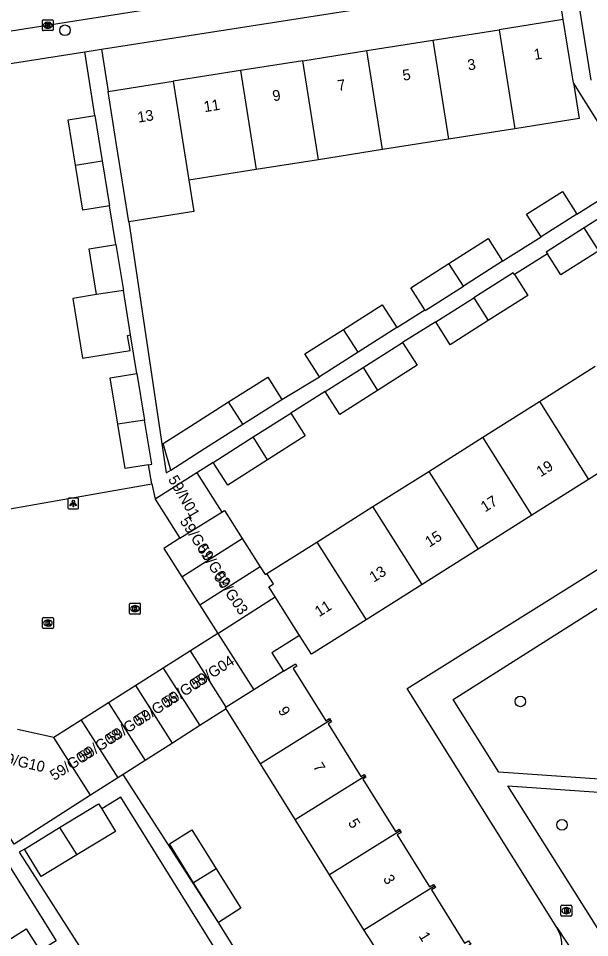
# Model space of a CAD drawing. Extents: x 160077 to 160945, y 386481 to 387498.
# Drawn here: x 160315.7 to 160368.6, y 387143.3 to 387228.4 of the extents above; entities that cross this region are included whole.
import ezdxf

# ---------------------------------------------------------------- set-up
doc = ezdxf.new("R2010")
doc.units = 0
for name, color, linetype in [('IMGEO_Boom', 7, 'Continuous'), ('IMGEO_Brandkraan', 7, 'Continuous'), ('IMGEO_Kolk', 7, 'Continuous'), ('IMGEO_Lichtpunt', 7, 'Continuous'), ('IMGEO_Pand', 7, 'Continuous'), ('IMGEO_Pand_nummerreeks', 7, 'Continuous'), ('IMGEO_Rijbaan_lokaal_open', 7, 'Continuous'), ('IMGEO_Voetpad_open', 7, 'Continuous')]:
    doc.layers.add(name, color=color, linetype=linetype)

msp = doc.modelspace()

# ---------------------------------------------------------------- linework, layer by layer
at = {"layer": 'IMGEO_Boom'}
for centre in [(160320.047, 387227.258), (160362.151, 387165.177), (160365.998, 387153.759)]:
    msp.add_circle(centre, 0.489, dxfattribs=at)
at = {"layer": 'IMGEO_Brandkraan'}
for p, q in [((160365.9, 387145.394), (160365.9, 387146.246)), ((160365.975, 387146.32), (160366.827, 387146.32)), ((160366.388, 387146.1), (160366.413, 387146.1)), ((160366.901, 387146.246), (160366.901, 387145.394)), ((160366.827, 387145.32), (160365.975, 387145.32)), ((160366.411, 387145.54), (160366.386, 387145.54))]:
    msp.add_line(p, q, dxfattribs=at)
for points in [[(160365.9, 387145.394), (160365.9, 387146.246)], [(160365.975, 387146.32), (160366.827, 387146.32)], [(160366.248, 387146.02), (160366.248, 387145.62), (160366.461, 387145.62)], [(160366.479, 387146.02), (160366.248, 387146.02)], [(160366.427, 387145.939), (160366.373, 387145.939), (160366.373, 387145.863)], [(160366.373, 387145.863), (160366.426, 387145.863)], [(160366.435, 387145.787), (160366.373, 387145.787), (160366.373, 387145.706)], [(160366.901, 387146.246), (160366.901, 387145.394)], [(160366.827, 387145.32), (160365.975, 387145.32)], [(160366.373, 387145.706), (160366.435, 387145.706)]]:
    msp.add_lwpolyline(points, dxfattribs=at)
for centre, radius, start, end in [((160365.977, 387146.244), 0.0765, 91.55205, 178.44795), ((160365.977, 387146.244), 0.0765, 91.55205, 178.44795), ((160366.428, 387145.901), 0.0379, 267.82845, 90.93552), ((160366.436, 387145.746), 0.0404, 269.87594, 90.50774), ((160366.483, 387145.875), 0.145, 59.4692, 91.53667), ((160366.508, 387145.922), 0.0922, 285.51372, 58.15012), ((160366.513, 387145.73), 0.105, 301.31148, 78.98903), ((160366.825, 387146.244), 0.0765, 1.55205, 88.44795), ((160366.825, 387146.244), 0.0765, 1.55205, 88.44795), ((160365.977, 387145.396), 0.0765, 181.55205, 268.44795), ((160365.977, 387145.396), 0.0765, 181.55205, 268.44795), ((160366.467, 387145.871), 0.251, 268.66757, 293.53466), ((160366.825, 387145.396), 0.0765, 271.55205, 358.44795), ((160366.825, 387145.396), 0.0765, 271.55205, 358.44795)]:
    msp.add_arc(centre, radius, start, end, dxfattribs=at)
for centre, major_axis, ratio, start_param, end_param in [((160366.387, 387145.82), (-0.387, 0.002), 0.722429, 4.712389, 7.853982), ((160366.412, 387145.82), (-0.39, 0.002), 0.717154, 1.570796, 4.712389)]:
    msp.add_ellipse(centre, major_axis=major_axis, ratio=ratio, start_param=start_param, end_param=end_param, dxfattribs=at)
at = {"layer": 'IMGEO_Kolk'}
for p, q in [((160318.032, 387228.223), (160318.884, 387228.223)), ((160317.957, 387227.297), (160317.957, 387228.149)), ((160318.468, 387227.443), (160318.443, 387227.443)), ((160318.445, 387228.003), (160318.47, 387228.003)), ((160318.958, 387228.149), (160318.958, 387227.297)), ((160318.884, 387227.223), (160318.032, 387227.223)), ((160326.012, 387173.333), (160326.012, 387174.185)), ((160326.087, 387174.259), (160326.939, 387174.259)), ((160326.5, 387174.039), (160326.525, 387174.039)), ((160327.013, 387174.185), (160327.013, 387173.333)), ((160326.939, 387173.259), (160326.087, 387173.259)), ((160326.523, 387173.479), (160326.498, 387173.479)), ((160317.97, 387171.999), (160317.97, 387172.851)), ((160318.045, 387172.925), (160318.897, 387172.925)), ((160318.481, 387172.145), (160318.456, 387172.145)), ((160318.458, 387172.705), (160318.483, 387172.705)), ((160318.971, 387172.851), (160318.971, 387171.999)), ((160318.897, 387171.925), (160318.045, 387171.925))]:
    msp.add_line(p, q, dxfattribs=at)
for points in [[(160318.032, 387228.223), (160318.884, 387228.223)], [(160317.957, 387227.297), (160317.957, 387228.149)], [(160318.278, 387227.923), (160318.401, 387227.923), (160318.401, 387227.772), (160318.531, 387227.923), (160318.695, 387227.923), (160318.549, 387227.772), (160318.702, 387227.523), (160318.55, 387227.523), (160318.465, 387227.687), (160318.401, 387227.62), (160318.401, 387227.523), (160318.278, 387227.523), (160318.278, 387227.923)], [(160318.958, 387228.149), (160318.958, 387227.297)], [(160318.884, 387227.223), (160318.032, 387227.223)], [(160326.012, 387173.333), (160326.012, 387174.185)], [(160326.087, 387174.259), (160326.939, 387174.259)], [(160326.333, 387173.959), (160326.456, 387173.959), (160326.456, 387173.808), (160326.586, 387173.959), (160326.75, 387173.959), (160326.604, 387173.808), (160326.757, 387173.559), (160326.605, 387173.559), (160326.52, 387173.723), (160326.456, 387173.656), (160326.456, 387173.559), (160326.333, 387173.559), (160326.333, 387173.959)], [(160327.013, 387174.185), (160327.013, 387173.333)], [(160326.939, 387173.259), (160326.087, 387173.259)], [(160317.97, 387171.999), (160317.97, 387172.851)], [(160318.045, 387172.925), (160318.897, 387172.925)], [(160318.291, 387172.625), (160318.414, 387172.625), (160318.414, 387172.474), (160318.544, 387172.625), (160318.708, 387172.625), (160318.562, 387172.474), (160318.715, 387172.225), (160318.563, 387172.225), (160318.478, 387172.389), (160318.414, 387172.322), (160318.414, 387172.225), (160318.291, 387172.225), (160318.291, 387172.625)], [(160318.971, 387172.851), (160318.971, 387171.999)], [(160318.897, 387171.925), (160318.045, 387171.925)]]:
    msp.add_lwpolyline(points, dxfattribs=at)
for centre, start, end in [((160318.034, 387228.147), 91.55205, 178.44795), ((160318.034, 387228.147), 91.55205, 178.44795), ((160318.882, 387228.147), 1.55205, 88.44795), ((160318.882, 387228.147), 1.55205, 88.44795), ((160318.034, 387227.299), 181.55205, 268.44795), ((160318.034, 387227.299), 181.55205, 268.44795), ((160318.882, 387227.299), 271.55205, 358.44795), ((160318.882, 387227.299), 271.55205, 358.44795), ((160326.089, 387174.183), 91.55205, 178.44795), ((160326.089, 387174.183), 91.55205, 178.44795), ((160326.937, 387174.183), 1.55205, 88.44795), ((160326.937, 387174.183), 1.55205, 88.44795), ((160326.089, 387173.335), 181.55205, 268.44795), ((160326.089, 387173.335), 181.55205, 268.44795), ((160326.937, 387173.335), 271.55205, 358.44795), ((160326.937, 387173.335), 271.55205, 358.44795), ((160318.047, 387172.849), 91.55205, 178.44795), ((160318.047, 387172.849), 91.55205, 178.44795), ((160318.895, 387172.849), 1.55205, 88.44795), ((160318.895, 387172.849), 1.55205, 88.44795), ((160318.047, 387172.001), 181.55205, 268.44795), ((160318.047, 387172.001), 181.55205, 268.44795), ((160318.895, 387172.001), 271.55205, 358.44795), ((160318.895, 387172.001), 271.55205, 358.44795)]:
    msp.add_arc(centre, 0.0765, start, end, dxfattribs=at)
for centre, major_axis, ratio, start_param, end_param in [((160318.444, 387227.723), (-0.387, 0.002), 0.722429, 4.712389, 7.853982), ((160318.469, 387227.723), (-0.39, 0.002), 0.717154, 1.570796, 4.712389), ((160326.499, 387173.759), (-0.387, 0.002), 0.722429, 4.712389, 7.853982), ((160326.524, 387173.759), (-0.39, 0.002), 0.717154, 1.570796, 4.712389), ((160318.457, 387172.425), (-0.387, 0.002), 0.722429, 4.712389, 7.853982), ((160318.482, 387172.425), (-0.39, 0.002), 0.717154, 1.570796, 4.712389)]:
    msp.add_ellipse(centre, major_axis=major_axis, ratio=ratio, start_param=start_param, end_param=end_param, dxfattribs=at)
at = {"layer": 'IMGEO_Lichtpunt'}
for p, q in [((160321.216, 387183.981), (160320.408, 387183.981)), ((160321.216, 387183.981), (160320.408, 387183.981)), ((160320.314, 387183.886), (160320.314, 387183.079)), ((160320.314, 387183.886), (160320.314, 387183.079)), ((160321.31, 387183.079), (160321.31, 387183.886)), ((160321.31, 387183.079), (160321.31, 387183.886)), ((160320.408, 387182.985), (160321.216, 387182.985)), ((160320.408, 387182.985), (160321.216, 387182.985))]:
    msp.add_line(p, q, dxfattribs=at)
for points in [[(160320.688, 387183.55), (160320.727, 387183.522), (160320.539, 387183.26), (160320.501, 387183.287), (160320.688, 387183.55)], [(160320.79, 387183.502), (160320.837, 387183.502), (160320.837, 387183.18), (160320.79, 387183.18), (160320.79, 387183.502)], [(160320.9, 387183.522), (160320.938, 387183.549), (160321.125, 387183.287), (160321.086, 387183.259), (160320.9, 387183.522)]]:
    msp.add_lwpolyline(points, dxfattribs=at)
msp.add_circle((160320.813, 387183.684), 0.0994, dxfattribs=at)
for centre, start, end in [((160320.408, 387183.886), 90, 180), ((160320.408, 387183.886), 90, 180), ((160321.216, 387183.886), 0, 90), ((160321.216, 387183.886), 0, 90), ((160320.408, 387183.079), 180, 270), ((160320.408, 387183.079), 180, 270), ((160321.216, 387183.079), 270, 0), ((160321.216, 387183.079), 270, 360)]:
    msp.add_arc(centre, 0.0946, start, end, dxfattribs=at)
at = {"layer": 'IMGEO_Pand'}
for points in [[(160366.123, 387228.252), (160360.206, 387227.315)], [(160367.052, 387222.386), (160366.905, 387223.314), (160366.123, 387228.252)], [(160354.05, 387226.34), (160360.206, 387227.315)], [(160360.206, 387227.315), (160361.655, 387218.154)], [(160347.963, 387225.377), (160354.05, 387226.34)], [(160354.05, 387226.34), (160355.499, 387217.179)], [(160342.046, 387224.44), (160347.963, 387225.377)], [(160349.412, 387216.215), (160347.963, 387225.377)], [(160342.046, 387224.44), (160336.282, 387223.527)], [(160343.495, 387215.278), (160342.046, 387224.44)], [(160336.282, 387223.527), (160330.053, 387222.541)], [(160336.282, 387223.527), (160337.731, 387214.366)], [(160324.041, 387221.589), (160330.053, 387222.541)], [(160330.053, 387222.541), (160331.502, 387213.38)], [(160367.052, 387222.386), (160367.574, 387219.091), (160361.655, 387218.154)], [(160325.949, 387209.543), (160325.492, 387212.428), (160324.823, 387216.651), (160324.041, 387221.589)], [(160321.013, 387214.794), (160320.33, 387218.972), (160322.797, 387219.376)], [(160322.797, 387219.376), (160323.483, 387215.18)], [(160361.655, 387218.154), (160355.499, 387217.179)], [(160355.499, 387217.179), (160349.412, 387216.215)], [(160349.412, 387216.215), (160343.495, 387215.278)], [(160321.013, 387214.794), (160323.483, 387215.18)], [(160324.164, 387211.017), (160321.697, 387210.613), (160321.013, 387214.794)], [(160323.483, 387215.18), (160324.164, 387211.017)], [(160343.495, 387215.278), (160337.731, 387214.366)], [(160337.731, 387214.366), (160331.502, 387213.38)], [(160331.502, 387213.38), (160331.958, 387210.495), (160325.949, 387209.543)], [(160364.063, 387208.164), (160362.728, 387210.26), (160366.057, 387212.352), (160367.369, 387210.259)], [(160371.707, 387211.291), (160368.06, 387208.972)], [(160367.369, 387210.259), (160364.063, 387208.164)], [(160368.06, 387208.972), (160364.551, 387206.741), (160364.646, 387206.592)], [(160369.395, 387206.858), (160368.06, 387208.972)], [(160355.543, 387205.694), (160359.167, 387207.998), (160360.51, 387205.889)], [(160322.974, 387202.802), (160322.281, 387207.041), (160324.748, 387207.445)], [(160324.748, 387207.445), (160325.444, 387203.188)], [(160369.395, 387206.858), (160365.894, 387204.632), (160364.646, 387206.592)], [(160353.314, 387201.402), (160352.011, 387203.448), (160355.543, 387205.694)], [(160356.894, 387203.59), (160355.543, 387205.694)], [(160360.51, 387205.889), (160356.894, 387203.59)], [(160361.602, 387204.654), (160361.487, 387204.835), (160357.839, 387202.515)], [(160361.602, 387204.654), (160362.83, 387202.726), (160359.174, 387200.402)], [(160353.314, 387201.402), (160353.354, 387201.339), (160356.894, 387203.59)], [(160322.974, 387202.802), (160320.773, 387202.442), (160321.677, 387196.916), (160326.061, 387197.633), (160325.831, 387199.039), (160326.115, 387199.086)], [(160325.444, 387203.188), (160322.974, 387202.802)], [(160326.115, 387199.086), (160325.444, 387203.188)], [(160345.799, 387199.585), (160349.387, 387201.866), (160350.73, 387199.757)], [(160354.331, 387200.285), (160357.839, 387202.515)], [(160357.839, 387202.515), (160359.174, 387200.402)], [(160359.174, 387200.402), (160355.674, 387198.176), (160354.331, 387200.285)], [(160343.574, 387195.207), (160342.231, 387197.316), (160345.799, 387199.585)], [(160347.14, 387197.475), (160345.799, 387199.585)], [(160350.73, 387199.757), (160347.14, 387197.475)], [(160347.621, 387196.062), (160351.268, 387198.381)], [(160351.268, 387198.381), (160352.611, 387196.272), (160348.956, 387193.948)], [(160347.14, 387197.475), (160343.574, 387195.207)], [(160344.112, 387193.831), (160347.621, 387196.062)], [(160347.621, 387196.062), (160348.956, 387193.948)], [(160363.906, 387192.912), (160369.074, 387196.177)], [(160324.936, 387190.81), (160324.234, 387195.1), (160326.701, 387195.504)], [(160326.701, 387195.504), (160327.405, 387191.197)], [(160335.18, 387192.876), (160338.787, 387195.169), (160340.102, 387193.101)], [(160348.956, 387193.948), (160345.455, 387191.722), (160344.112, 387193.831)], [(160329.833, 387186.572), (160329.136, 387189.033), (160331.64, 387190.625), (160335.18, 387192.876)], [(160336.495, 387190.808), (160335.18, 387192.876)], [(160336.495, 387190.808), (160340.102, 387193.101)], [(160358.674, 387189.608), (160363.906, 387192.912)], [(160363.906, 387192.912), (160368.454, 387185.713)], [(160337.449, 387189.637), (160340.915, 387191.841)], [(160340.915, 387191.841), (160342.258, 387189.732), (160338.784, 387187.523)], [(160327.405, 387191.197), (160324.936, 387190.81)], [(160327.763, 387187.064), (160325.606, 387186.711), (160324.936, 387190.81)], [(160327.763, 387187.064), (160328.073, 387187.115), (160327.405, 387191.197)], [(160329.833, 387186.572), (160332.955, 387188.557), (160336.495, 387190.808)], [(160333.759, 387187.291), (160337.449, 387189.637)], [(160338.784, 387187.523), (160337.449, 387189.637)], [(160353.687, 387186.458), (160358.674, 387189.608)], [(160363.222, 387182.408), (160358.674, 387189.608)], [(160373.621, 387188.977), (160368.454, 387185.713)], [(160338.784, 387187.523), (160335.102, 387185.182), (160333.759, 387187.291)], [(160332.236, 387186.322), (160328.383, 387183.872)], [(160332.236, 387186.322), (160334.55, 387182.682)], [(160348.524, 387183.196), (160353.687, 387186.458)], [(160353.687, 387186.458), (160358.235, 387179.258)], [(160368.454, 387185.713), (160363.222, 387182.408)], [(160328.383, 387183.872), (160330.678, 387180.264)], [(160343.334, 387179.918), (160348.524, 387183.196)], [(160353.072, 387175.997), (160348.524, 387183.196)], [(160330.678, 387180.264), (160334.55, 387182.682)], [(160334.55, 387182.682), (160334.789, 387182.831), (160336.426, 387180.256)], [(160363.222, 387182.408), (160358.235, 387179.258)], [(160330.678, 387180.264), (160329.176, 387179.326), (160330.842, 387176.706)], [(160330.842, 387176.706), (160336.426, 387180.256)], [(160336.426, 387180.256), (160338.092, 387177.636)], [(160338.712, 387176.999), (160343.334, 387179.918)], [(160343.334, 387179.918), (160347.882, 387172.719)], [(160358.235, 387179.258), (160353.072, 387175.997)], [(160338.092, 387177.636), (160332.509, 387174.085)], [(160338.092, 387177.636), (160338.559, 387176.902), (160338.712, 387176.999)], [(160330.842, 387176.706), (160332.509, 387174.085)], [(160339.488, 387174.844), (160339.319, 387175.112), (160338.892, 387175.788), (160339.313, 387176.054), (160338.712, 387176.999)], [(160353.072, 387175.997), (160347.882, 387172.719)], [(160334.175, 387171.465), (160339.488, 387174.844)], [(160341.734, 387171.283), (160339.488, 387174.844)], [(160332.509, 387174.085), (160334.175, 387171.465)], [(160347.882, 387172.719), (160342.839, 387169.533), (160341.734, 387171.283)], [(160334.175, 387171.465), (160331.649, 387169.859)], [(160334.175, 387171.465), (160337.498, 387166.239)], [(160341.734, 387171.283), (160339.181, 387169.66), (160340.261, 387167.961)], [(160331.649, 387169.859), (160329.122, 387168.252)], [(160334.957, 387164.656), (160331.649, 387169.859)], [(160329.122, 387168.252), (160326.596, 387166.646)], [(160329.122, 387168.252), (160332.502, 387162.937)], [(160340.261, 387167.961), (160337.498, 387166.239)], [(160340.261, 387167.961), (160341.361, 387168.644), (160341.499, 387168.424), (160341.153, 387168.208), (160344.162, 387163.378), (160344.504, 387163.591), (160344.598, 387163.44)], [(160326.596, 387166.646), (160324.07, 387165.04)], [(160329.979, 387161.326), (160326.596, 387166.646)], [(160337.498, 387166.239), (160334.957, 387164.656)], [(160324.07, 387165.04), (160321.543, 387163.433)], [(160324.07, 387165.04), (160327.456, 387159.714)], [(160334.947, 387164.498), (160332.502, 387162.937)], [(160334.947, 387164.498), (160334.879, 387164.607), (160334.957, 387164.656)], [(160338.124, 387159.406), (160334.947, 387164.498)], [(160321.543, 387163.433), (160319.017, 387161.827)], [(160321.543, 387163.433), (160324.932, 387158.103)], [(160332.502, 387162.937), (160329.979, 387161.326)], [(160344.598, 387163.44), (160338.124, 387159.406)], [(160344.598, 387163.44), (160344.69, 387163.292), (160344.372, 387163.094), (160347.41, 387158.217), (160347.722, 387158.411), (160347.797, 387158.29)], [(160319.017, 387161.827), (160315.654, 387162.575)], [(160322.409, 387156.492), (160315.34, 387151.978), (160309.181, 387161.663)], [(160322.409, 387156.492), (160319.017, 387161.827)], [(160329.979, 387161.326), (160327.456, 387159.714)], [(160327.456, 387159.714), (160325.437, 387158.426)], [(160341.33, 387154.259), (160338.124, 387159.406)], [(160324.932, 387158.103), (160322.409, 387156.492)], [(160325.437, 387158.426), (160324.932, 387158.103)], [(160341.33, 387154.259), (160347.797, 387158.29)], [(160347.797, 387158.29), (160347.873, 387158.168), (160347.574, 387157.982), (160350.593, 387153.136), (160350.937, 387153.35), (160351.029, 387153.202)], [(160319.551, 387153.511), (160323.151, 387155.708), (160323.44, 387155.235)], [(160323.44, 387155.235), (160324.712, 387153.151), (160321.143, 387150.973)], [(160344.516, 387149.144), (160341.33, 387154.259)], [(160316.293, 387151.523), (160319.551, 387153.511)], [(160319.551, 387153.511), (160321.143, 387150.973)], [(160331.939, 387148.405), (160329.697, 387151.997), (160331.78, 387153.297), (160334.022, 387149.704)], [(160351.029, 387153.202), (160344.516, 387149.144)], [(160351.029, 387153.202), (160351.121, 387153.054), (160350.751, 387152.824), (160353.747, 387148.014), (160354.116, 387148.244), (160354.203, 387148.105)], [(160321.143, 387150.973), (160317.854, 387148.965), (160316.293, 387151.523)], [(160334.022, 387149.704), (160331.939, 387148.405)], [(160334.022, 387149.704), (160336.311, 387146.037), (160334.228, 387144.737)], [(160347.691, 387144.048), (160344.516, 387149.144)], [(160334.228, 387144.737), (160331.939, 387148.405)], [(160354.203, 387148.105), (160354.291, 387147.964), (160353.929, 387147.738), (160356.994, 387142.817), (160357.357, 387143.043), (160357.563, 387142.711), (160351.05, 387138.654), (160348.407, 387142.898), (160347.691, 387144.048)], [(160347.691, 387144.048), (160354.203, 387148.105)], [(160312.804, 387141.83), (160316.456, 387144.133), (160317.74, 387142.096)]]:
    msp.add_lwpolyline(points, dxfattribs=at)
at = {"layer": 'IMGEO_Rijbaan_lokaal_open'}
for points in [[(160352.22, 387232.997), (160332.717, 387229.958), (160308.158, 387226.11)], [(160313.355, 387182.727), (160328.071, 387185.305)], [(160328.071, 387185.305), (160328.383, 387183.872)]]:
    msp.add_lwpolyline(points, dxfattribs=at)
at = {"layer": 'IMGEO_Voetpad_open'}
for points in [[(160323.427, 387225.514), (160365.52, 387232.102)], [(160366.123, 387228.252), (160365.52, 387232.102)], [(160367.115, 387232.352), (160368.655, 387222.649)], [(160296.864, 387221.356), (160321.874, 387225.271)], [(160321.874, 387225.271), (160323.427, 387225.514)], [(160322.797, 387219.376), (160321.874, 387225.271)], [(160323.427, 387225.514), (160324.041, 387221.589)], [(160367.369, 387210.259), (160372.599, 387213.537), (160367.052, 387222.386)], [(160324.748, 387207.445), (160324.164, 387211.017)], [(160325.949, 387209.543), (160329.416, 387186.306), (160329.833, 387186.572)], [(160360.51, 387205.889), (160360.784, 387206.084), (160364.063, 387208.164)], [(160364.646, 387206.592), (160361.602, 387204.654)], [(160350.73, 387199.757), (160353.314, 387201.402)], [(160354.331, 387200.285), (160351.268, 387198.381)], [(160326.701, 387195.504), (160326.115, 387199.086)], [(160340.102, 387193.101), (160343.574, 387195.207)], [(160344.112, 387193.831), (160340.915, 387191.841)], [(160365.51, 387144.26), (160351.677, 387166.384), (160388.058, 387189.131)], [(160328.071, 387185.305), (160327.763, 387187.064)], [(160333.759, 387187.291), (160332.236, 387186.322)], [(160371.697, 387157.833), (160362.388, 387158.472), (160360.153, 387158.624), (160355.944, 387165.36), (160373.598, 387176.533)], [(160334.228, 387144.737), (160325.437, 387158.426)], [(160361.003, 387157.364), (160371.582, 387156.625)], [(160369.458, 387143.924), (160361.003, 387157.364)], [(160336.535, 387138.132), (160325.196, 387156.306), (160323.44, 387155.235)], [(160312.905, 387153.093), (160319.242, 387143.043), (160317.74, 387142.096)], [(160316.293, 387151.523), (160315.822, 387151.223), (160321.391, 387142.502), (160318.35, 387140.604)], [(160336.058, 387141.786), (160334.228, 387144.737)], [(160365.51, 387144.26), (160365.513, 387144.26), (160368.801, 387139.312)]]:
    msp.add_lwpolyline(points, dxfattribs=at)
msp.add_arc((160362.998, 387142.644), 2.987, 299.34927, 32.75721, dxfattribs=at)

# ---------------------------------------------------------------- texts
at = {"layer": 'IMGEO_Pand_nummerreeks'}
for s, rotation, p in [('1', 8.99544, (160363.471, 387224.511)), ('3', 8.99717, (160357.346, 387223.541)), ('5', 8.99717, (160351.334, 387222.589)), ('7', 8.99717, (160345.323, 387221.637)), ('9', 8.99717, (160339.311, 387220.685)), ('11', 8.99717, (160332.957, 387219.68)), ('13', 8.99544, (160326.833, 387218.711)), ('19', 32.27952, (160364.029, 387185.899)), ('59/N01', 300.14139, (160329.546, 387185.73)), ('17', 32.27952, (160358.883, 387182.648)), ('59/G01', 302.90524, (160330.623, 387181.847)), ('15', 32.27952, (160353.737, 387179.398)), ('59/G02', 302.90524, (160332.232, 387179.31)), ('59/G03', 304.50852, (160333.749, 387176.708)), ('13', 32.27952, (160348.591, 387176.147)), ('11', 32.27952, (160343.54, 387172.957)), ('59/G04', 32.95128, (160332.131, 387166.276)), ('59/G05', 32.95128, (160329.517, 387164.582)), ('59/G06', 32.95128, (160326.904, 387162.888)), ('9', 301.95845, (160339.705, 387164.334)), ('59/G07', 32.95128, (160324.291, 387161.195)), ('59/G08', 32.9508, (160321.68, 387159.502)), ('59/G10', 346.86598, (160313.779, 387159.611)), ('59/G09', 32.95128, (160319.062, 387157.805)), ('7', 301.95845, (160342.942, 387159.145)), ('5', 301.95845, (160346.179, 387153.956)), ('3', 301.95845, (160349.416, 387148.767)), ('1', 301.95845, (160352.714, 387143.481))]:
    msp.add_text(s, height=1, rotation=rotation, dxfattribs=at).set_placement(p)

doc.saveas('drawing.dxf')
